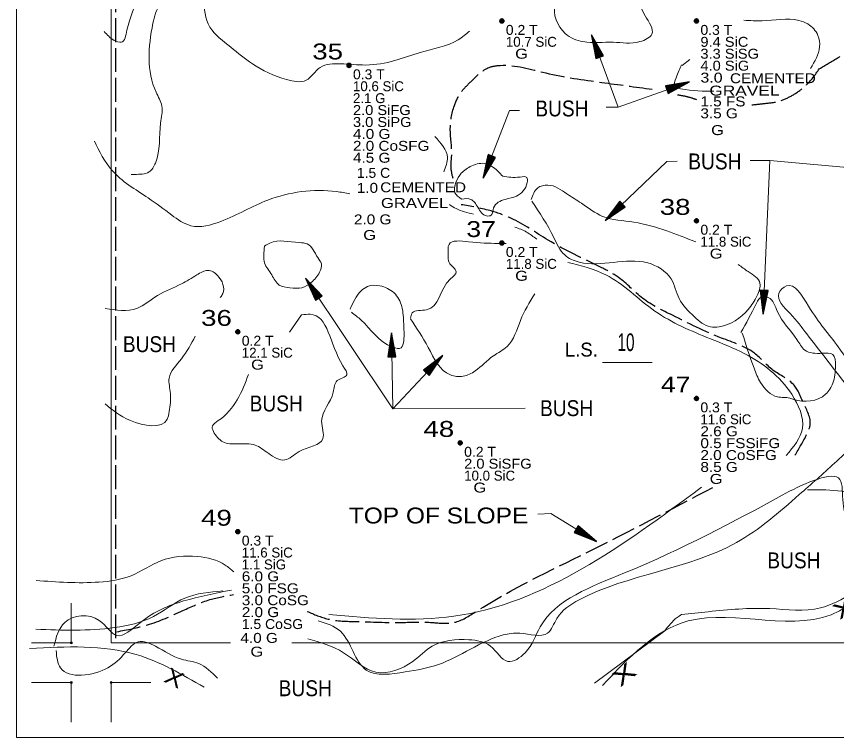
# Model space of a CAD drawing. Extents: x -496 to 480, y -450 to 700.
# Drawn here: x -450 to -37.5, y -450 to -87.1 of the extents above; entities that cross this region are included whole.
import ezdxf
from ezdxf.enums import TextEntityAlignment as Align

# ---------------------------------------------------------------- set-up
doc = ezdxf.new("R2010")
doc.units = 0
doc.header["$LTSCALE"] = 2
doc.header["$PDMODE"] = 32
doc.header["$PDSIZE"] = 1
doc.linetypes.add('LONG_DASHED', pattern=[7.5, 6, -1.5])
for name, color, linetype, lineweight in [('1', 7, 'Continuous', 13), ('2', 7, 'Continuous', 35), ('3', 7, 'Continuous', 13), ('4', 7, 'Continuous', 25)]:
    doc.layers.add(name, color=color, linetype=linetype, lineweight=lineweight)

msp = doc.modelspace()

# ---------------------------------------------------------------- linework, layer by layer
at = {"layer": '1'}
for p, q in [((-402.391, 402.339), (-402.391, -402.333)), ((-155.262, -261.192), (-130.262, -261.192)), ((-422.391, -402.333), (-422.391, -382.333)), ((-422.391, -402.333), (-442.391, -402.333)), ((-402.391, -402.333), (-342.324, -402.333)), ((-311.567, -402.333), (402.281, -402.333)), ((-422.391, -422.333), (-442.391, -422.333)), ((-422.391, -422.333), (-422.391, -442.333)), ((-402.391, -422.333), (-402.391, -442.333)), ((-450.017, -450.027), (449.983, -450.027))]:
    msp.add_line(p, q, dxfattribs=at)
for points in [[(449.983, -450.027), (449.983, 399.973), (449.983, 699.973), (-450.017, 699.973), (-450.017, 49.973), (-450.017, -450.027)], [(-402.391, -422.333), (-382.391, -422.333), (-402.391, -422.333)]]:
    msp.add_lwpolyline(points, dxfattribs=at)
for p in [(-422.391, -402.333), (-422.391, -422.333), (-402.391, -422.333)]:
    msp.add_point(p, dxfattribs=at)
at = {"layer": '2', "linetype": 'LONG_DASHED', "lineweight": 25}
msp.add_line((-400, -400), (-400, 302.339), dxfattribs=at)
at = {"layer": '2'}
for centre in [(-205.849, -89.361), (-107.989, -89.361), (-282.739, -111.711), (-107.989, -189.936), (-205.849, -201.111), (-338.659, -245.811), (-107.989, -279.336), (-226.819, -301.686), (-338.659, -346.386)]:
    msp.add_circle(centre, 1, dxfattribs=at)
for points in [[(-205.86, -88.474), (-205.129, -88.878), (-204.978, -89.727), (-205.663, -90.255), (-206.472, -90.024), (-206.758, -89.266), (-206.511, -88.704), (-205.938, -88.536), (-205.264, -89.03), (-205.281, -89.772), (-205.798, -90.03), (-206.32, -89.861), (-206.545, -89.215), (-205.961, -88.749), (-205.523, -89.283), (-205.562, -89.766), (-206.191, -89.631), (-206.045, -88.996), (-205.753, -89.547)], [(-108, -88.474), (-107.269, -88.878), (-107.118, -89.727), (-107.803, -90.255), (-108.612, -90.024), (-108.898, -89.266), (-108.651, -88.704), (-108.078, -88.536), (-107.404, -89.03), (-107.421, -89.772), (-107.938, -90.03), (-108.46, -89.861), (-108.685, -89.215), (-108.101, -88.749), (-107.663, -89.283), (-107.702, -89.766), (-108.331, -89.631), (-108.185, -88.996), (-107.893, -89.547)], [(-282.75, -110.824), (-282.019, -111.228), (-281.868, -112.077), (-282.553, -112.605), (-283.362, -112.374), (-283.648, -111.616), (-283.401, -111.054), (-282.828, -110.886), (-282.154, -111.38), (-282.171, -112.122), (-282.688, -112.38), (-283.21, -112.211), (-283.435, -111.565), (-282.851, -111.099), (-282.413, -111.633), (-282.452, -112.116), (-283.081, -111.981), (-282.935, -111.346), (-282.643, -111.897)], [(-108, -189.049), (-107.269, -189.453), (-107.118, -190.302), (-107.803, -190.83), (-108.612, -190.599), (-108.898, -189.841), (-108.651, -189.279), (-108.078, -189.111), (-107.404, -189.605), (-107.421, -190.347), (-107.938, -190.605), (-108.46, -190.436), (-108.685, -189.79), (-108.101, -189.324), (-107.663, -189.858), (-107.702, -190.341), (-108.331, -190.206), (-108.185, -189.571), (-107.893, -190.122)], [(-205.86, -200.224), (-205.129, -200.628), (-204.978, -201.477), (-205.663, -202.005), (-206.472, -201.774), (-206.758, -201.016), (-206.511, -200.454), (-205.938, -200.286), (-205.264, -200.78), (-205.281, -201.522), (-205.798, -201.78), (-206.32, -201.611), (-206.545, -200.965), (-205.961, -200.499), (-205.523, -201.033), (-205.562, -201.516), (-206.191, -201.381), (-206.045, -200.746), (-205.753, -201.297)], [(-338.67, -244.924), (-337.939, -245.328), (-337.788, -246.177), (-338.473, -246.705), (-339.282, -246.474), (-339.568, -245.716), (-339.321, -245.154), (-338.748, -244.986), (-338.074, -245.48), (-338.091, -246.222), (-338.608, -246.48), (-339.13, -246.311), (-339.355, -245.665), (-338.771, -245.199), (-338.333, -245.733), (-338.372, -246.216), (-339.001, -246.081), (-338.855, -245.446), (-338.563, -245.997)], [(-108, -278.449), (-107.269, -278.853), (-107.118, -279.702), (-107.803, -280.23), (-108.612, -279.999), (-108.898, -279.241), (-108.651, -278.679), (-108.078, -278.511), (-107.404, -279.005), (-107.421, -279.747), (-107.938, -280.005), (-108.46, -279.836), (-108.685, -279.19), (-108.101, -278.724), (-107.663, -279.258), (-107.702, -279.741), (-108.331, -279.606), (-108.185, -278.971), (-107.893, -279.522)], [(-226.83, -300.799), (-226.099, -301.203), (-225.948, -302.052), (-226.633, -302.58), (-227.442, -302.349), (-227.728, -301.591), (-227.481, -301.029), (-226.908, -300.861), (-226.234, -301.355), (-226.251, -302.097), (-226.768, -302.355), (-227.29, -302.186), (-227.515, -301.54), (-226.931, -301.074), (-226.493, -301.608), (-226.532, -302.091), (-227.161, -301.956), (-227.015, -301.321), (-226.723, -301.872)], [(-338.67, -345.499), (-337.939, -345.903), (-337.788, -346.752), (-338.473, -347.28), (-339.282, -347.049), (-339.568, -346.291), (-339.321, -345.729), (-338.748, -345.561), (-338.074, -346.055), (-338.091, -346.797), (-338.608, -347.055), (-339.13, -346.886), (-339.355, -346.24), (-338.771, -345.774), (-338.333, -346.308), (-338.372, -346.791), (-339.001, -346.656), (-338.855, -346.021), (-338.563, -346.572)]]:
    msp.add_spline(points, degree=3, dxfattribs=at)
at = {"layer": '2', "linetype": 'LONG_DASHED', "lineweight": 25}
for points in [[(-46.213, -113.44), (-37.202, -108.011), (-28.328, -103.466), (-16.725, -100.739), (-6.714, -99.603), (-5.46, -99.466)], [(-230.408, -168.6), (-231.437, -162.433), (-231.094, -157.294), (-231.78, -144.275), (-229.722, -131.941), (-225.949, -124.746), (-221.147, -119.607), (-212.229, -112.754), (-206.74, -111.727), (-183.759, -115.495), (-155.632, -120.292), (-130.25, -123.718)], [(-80.171, -131.598), (-73.997, -130.913), (-65.764, -129.542), (-59.247, -126.459), (-53.073, -122.005), (-46.213, -113.44)], [(-117.559, -126.459), (-112.413, -127.487), (-107.954, -128.857)], [(-58.437, -307.961), (-52.485, -297.343), (-50.784, -292.671), (-54.185, -281.629), (-58.863, -272.71), (-69.493, -265.065), (-78.847, -256.571), (-95.43, -248.926), (-120.092, -237.459), (-134.974, -228.965), (-147.305, -218.347), (-156.234, -213.25), (-182.596, -199.66), (-201.305, -188.617), (-211.935, -184.795), (-226.392, -181.822)], [(-303.779, -386.532), (-293.149, -390.354), (-279.117, -391.628), (-256.156, -392.053), (-241.699, -392.053), (-233.195, -392.478), (-229.794, -392.053), (-218.738, -386.532), (-163.037, -356.802), (-99.682, -324.1)], [(-399.449, -396.725), (-384.142, -393.327), (-366.283, -386.107), (-352.677, -380.586), (-340.771, -378.038)]]:
    msp.add_spline(points, degree=3, dxfattribs=at)
at = {"layer": '3'}
for p, q in [((-115.121, -111.726), (-111.273, -108.701)), ((-312.726, -246.028), (-306.569, -237.269)), ((-123.946, -396.28), (-159.286, -422.632))]:
    msp.add_line(p, q, dxfattribs=at)
for points in [[(-405.865, -94.67), (-400.768, -99.124), (-397.265, -100.078), (-394.398, -94.034), (-389.302, -77.808), (-387.709, -27.222), (-386.117, -18.314), (-377.517, -13.224), (-373.695, -15.133), (-364.458, -27.222), (-360.954, -33.267), (-359.361, -63.491), (-359.043, -73.99), (-363.183, -76.535), (-373.376, -78.762), (-377.517, -81.308), (-381.339, -90.534), (-379.746, -125.212), (-376.88, -132.211), (-377.517, -140.801), (-380.065, -160.845), (-383.25, -165.299), (-390.576, -166.571), (-392.345, -166.607)], [(-222.064, -94.436), (-227.814, -98.806), (-246.925, -105.169), (-259.666, -109.305), (-274.317, -111.532), (-287.058, -110.895), (-297.251, -112.804), (-304.258, -119.167), (-314.132, -118.849), (-331.332, -110.895), (-342.161, -102.624), (-352.672, -92.443), (-352.991, -61.582), (-351.717, -53.947)], [(-171.436, -58.401), (-164.429, -56.174), (-153.281, -56.174), (-142.133, -66.355), (-133.851, -86.716), (-130.348, -95.942), (-136.4, -99.76), (-149.777, -100.078), (-165.066, -99.76), (-173.985, -95.624), (-179.081, -80.989), (-173.348, -71.445), (-171.755, -59.037)], [(-84.103, -88.974), (-74.903, -89.31), (-56.461, -89.088), (-52.017, -90.863), (-46.907, -96.634), (-46.018, -102.404), (-50.623, -113.272)], [(-99.282, -124.751), (-116.009, -123.488), (-118.898, -122.379), (-118.231, -117.94), (-115.565, -111.504)], [(-239.609, -147.485), (-233.205, -158.023), (-235.009, -165.254)], [(-410.822, -149.827), (-402.028, -164.468), (-383.748, -178.431), (-371.919, -187.023), (-362.242, -192.393), (-347.187, -190.245), (-323.531, -179.505), (-289.121, -175.208), (-282.297, -176.356)], [(-226.078, -178.965), (-229.459, -175.789), (-228.952, -170.557), (-226.248, -165.999), (-221.01, -162.286), (-213.575, -161.274), (-210.026, -163.13), (-205.423, -167.503)], [(-226.078, -178.965), (-221.488, -179.173), (-217.941, -183.133), (-213.559, -187.509), (-211.265, -187.092), (-210.013, -183.341), (-204.171, -179.173), (-198.538, -177.506), (-193.113, -170.629), (-193.322, -168.128), (-196.66, -167.92), (-205.423, -167.503)], [(-191.126, -179.272), (-187.827, -173.414), (-182.696, -171.95), (-173.166, -176.343), (-165.836, -181.102), (-155.207, -187.692), (-139.447, -190.62), (-122.953, -195.014), (-108.348, -200.566)], [(-86.95, -211.951), (-81.903, -215.515), (-76.039, -221.372), (-77.505, -227.596), (-81.903, -234.552), (-96.564, -243.338), (-100.962, -243.338), (-109.026, -238.213), (-116.723, -229.06), (-120.754, -219.176), (-132.483, -211.122), (-166.936, -210.756), (-174.266, -207.095), (-179.764, -198.308), (-190.759, -180.004)], [(-232.139, -181.803), (-228.904, -183.801), (-220.095, -186.529)], [(-199.396, -193.069), (-193.419, -195.616), (-188.351, -199.186)], [(-325.167, -202.695), (-322.492, -201.137), (-307.778, -200.914), (-303.765, -201.582), (-298.414, -208.485), (-296.631, -211.603), (-297.522, -215.834), (-301.758, -220.955), (-306.44, -223.627), (-312.459, -223.627), (-317.81, -222.291), (-321.6, -217.17), (-325.167, -211.157), (-325.167, -202.695)], [(-251.82, -238.992), (-250.928, -236.32), (-243.794, -234.761), (-231.755, -219.174), (-228.857, -215.611), (-230.195, -213.384), (-232.424, -210.935), (-232.87, -206.926), (-232.424, -201.805), (-222.615, -200.469), (-207.678, -201.359), (-203.722, -201.411)], [(-172.722, -210.874), (-153.632, -217.097), (-128.9, -235.356), (-100.942, -249.319), (-83.737, -256.837), (-60.081, -277.244), (-54.704, -294.429), (-62.794, -308.026)], [(-405.351, -234.023), (-389.429, -234.023), (-379.031, -227.532), (-367.008, -221.689), (-359.209, -217.145), (-353.685, -214.873), (-348.811, -217.47), (-346.212, -226.558), (-347.468, -228.548)], [(-282.198, -234.348), (-276.674, -225.26), (-273.424, -222.988), (-267.25, -222.663), (-260.102, -226.233), (-256.202, -233.049), (-255.227, -241.813), (-255.227, -250.251), (-256.527, -253.822), (-260.752, -253.497), (-276.674, -239.865), (-281.548, -235.97)], [(-25.045, -283.284), (-31.126, -274.748), (-52.532, -246.859), (-60.908, -236.633), (-66.492, -226.408), (-62.769, -222.689), (-51.601, -232.915), (-36.71, -253.366), (-25.542, -266.381), (-1.344, -271.029), (59.151, -269.17), (76.834, -267.311), (88.933, -264.522), (91.725, -263.592), (101.963, -260.803), (141.052, -260.803), (168.042, -271.959), (185.632, -271.816)], [(-189.29, -226.613), (-196.531, -240.106), (-203.219, -253.244), (-210.13, -257.92), (-219.271, -265.491), (-225.29, -268.164), (-231.755, -267.496), (-242.902, -253.689), (-251.82, -239.215)], [(-85.592, -246.145), (-77.732, -231.425), (-75.113, -228.154), (-71.838, -228.481), (-67.253, -235.678), (-57.428, -249.743), (-53.498, -254.977), (-44.656, -256.612), (-39.417, -257.267), (-38.107, -262.827), (-39.417, -271.659), (-43.019, -277.22), (-59.066, -279.837), (-61.031, -279.183), (-67.253, -278.529), (-75.767, -271.332), (-79.042, -264.136), (-84.937, -246.472)], [(-306.569, -237.269), (-302.344, -236.944), (-285.772, -262.909), (-283.823, -267.453), (-288.697, -270.375), (-290.646, -276.217), (-296.495, -290.822), (-295.845, -299.586), (-307.868, -306.077), (-315.017, -310.296), (-323.141, -307.051), (-329.965, -302.831), (-338.738, -302.182), (-346.212, -301.208), (-348.811, -298.936), (-351.411, -293.094), (-348.486, -290.498), (-333.258, -267.239)], [(-360.034, -247.993), (-367.008, -259.339), (-373.182, -269.076), (-372.532, -276.866), (-373.182, -285.954), (-374.157, -289.849), (-392.679, -290.498), (-405.351, -282.059)], [(-298.323, -391.257), (-287.066, -396.527), (-274.036, -416.049), (-254.492, -416.978), (-237.739, -413.26), (-205.165, -398.386), (-196.789, -397.457), (-182.828, -397.457), (-178.175, -390.02), (-167.007, -380.723), (-87.898, -351.905), (-56.254, -327.736), (-38.571, -311.932), (-29.348, -303.089)], [(-155.247, -423.81), (-112.142, -391.328), (-35.973, -386.256), (9.729, -352.442), (55.43, -355.824), (74.049, -337.226), (197.613, -337.226), (216.232, -359.205), (263.626, -357.515), (267.5, -350.576)], [(88.896, -303.619), (49.044, -310.618), (19.602, -316.132), (-0.64, -326.242), (-10.761, -328.08), (-42.964, -325.323), (-52.165, -325.323)], [(-303.447, -400.25), (-285.473, -407.314), (-269.167, -417.086), (-250.688, -411.657), (-240.904, -404.057), (-222.425, -400.799), (-211.554, -404.057), (-202.858, -411.657), (-194.162, -407.314), (-186.552, -394.284), (-144.158, -367.14), (-64.804, -328.052), (-48.498, -320.451), (-36.541, -319.365), (-34.367, -330.223), (-31.106, -341.081), (-16.974, -329.138), (-8.336, -324.238)], [(-105.388, -324.019), (-229.979, -388.946), (-292.861, -388.127)], [(88.718, -334.024), (76.16, -334.535), (70.748, -335.693), (65.336, -342.257), (58.378, -348.821), (51.807, -352.296), (33.638, -351.524), (20.109, -349.98), (14.31, -349.593), (4.646, -351.138), (-2.698, -358.474), (-29.371, -377.394), (-45.607, -384.73), (-71.12, -385.116), (-102.045, -386.66), (-115.443, -388.108)], [(-340.738, -366.543), (-345.037, -363.169), (-359.016, -358.873), (-377.296, -361.021), (-392.35, -368.539), (-408.48, -371.761), (-440.132, -370.951)], [(-440.174, -395.508), (-400.61, -394.668), (-381.066, -389.09), (-365.244, -379.794), (-346.274, -376.213)], [(-431.137, -404.057), (-425.701, -392.113), (-408.309, -391.027), (-399.612, -398.628), (-387.655, -392.113), (-365.914, -381.255), (-341.779, -375.801)], [(-123.946, -396.28), (-117.726, -389.601), (-115.443, -388.108)], [(-443.356, -405.126), (-389.736, -408.235), (-355.532, -424.724)], [(-348.927, -420.064), (-358.305, -412.743), (-367.001, -410.571), (-380.046, -404.057), (-388.742, -401.885), (-395.264, -407.314), (-403.961, -414.914), (-427.875, -414.914), (-430.05, -406.228)]]:
    msp.add_spline(points, degree=3, dxfattribs=at)
at = {"layer": '4', "lineweight": 13}
for p, q in [((-147.335, -132.749), (-111.512, -119.922)), ((-71.087, -159.656), (-74.464, -236.991)), ((-260.731, -284.569), (-261.439, -246.399)), ((-260.731, -284.569), (-235.609, -257.709))]:
    msp.add_line(p, q, dxfattribs=at)
for points in [[(-153.418, -132.749), (-147.335, -132.749), (-160.853, -96.292)], [(-197.015, -134.437), (-202.084, -134.437), (-215.265, -168.531)], [(-117.639, -159.897), (-122.945, -160.138), (-153.819, -189.771)], [(-80.976, -159.656), (-71.087, -159.656), (-24.776, -163.751)], [(-194.21, -284.216), (-260.731, -284.569), (-304.606, -218.832)], [(-187.701, -337.511), (-181.249, -337.31), (-158.264, -351.407)]]:
    msp.add_lwpolyline(points, dxfattribs=at)
at = {"layer": '4'}
for points in [[(-160.853, -96.292), (-158.557, -108.239), (-154.806, -106.848)], [(-111.512, -119.922), (-123.483, -122.084), (-122.135, -125.85)], [(-215.265, -168.531), (-209.072, -158.06), (-212.803, -156.617)], [(-153.819, -189.771), (-143.776, -182.904), (-146.546, -180.018)], [(-304.606, -218.832), (-299.608, -229.924), (-296.281, -227.703)], [(-74.464, -236.991), (-71.942, -225.09), (-75.938, -224.916)], [(-261.439, -246.399), (-263.216, -258.434), (-259.217, -258.36)], [(-235.609, -257.709), (-245.266, -265.107), (-242.345, -267.839)], [(-158.264, -351.407), (-167.447, -343.429), (-169.539, -346.838)]]:
    msp.add_lwpolyline(points, close=True, dxfattribs=at)
for points in [[(-158.48, -108.106), (-160.655, -96.83), (-155.017, -106.753), (-158.332, -108.004), (-160.399, -97.521), (-155.245, -106.63), (-158.251, -107.791), (-160.128, -98.251), (-155.517, -106.523), (-158.094, -107.595), (-159.84, -99.087), (-155.782, -106.367), (-157.965, -107.315), (-159.493, -100.09), (-156.093, -106.275), (-157.797, -107.023), (-159.115, -101.17), (-156.495, -106.125), (-157.666, -106.697), (-158.739, -102.37), (-156.858, -105.891), (-157.535, -106.303), (-158.201, -103.761), (-157.336, -105.654)], [(-123.351, -122.162), (-112.052, -120.114), (-122.037, -125.64), (-123.251, -122.311), (-112.746, -120.363), (-121.912, -125.414), (-123.039, -122.395), (-113.478, -120.625), (-121.802, -125.143), (-122.844, -122.554), (-114.318, -120.904), (-121.643, -124.879), (-122.566, -122.686), (-115.325, -121.239), (-121.547, -124.569), (-122.276, -122.857), (-116.409, -121.605), (-121.393, -124.17), (-121.952, -122.992), (-117.613, -121.968), (-121.155, -123.809), (-121.559, -123.127), (-119.01, -122.49), (-120.912, -123.334)], [(-209.218, -158.108), (-215.057, -167.996), (-212.709, -156.828), (-209.396, -158.087), (-214.791, -167.309), (-212.619, -157.072), (-209.598, -158.192), (-214.511, -166.583), (-212.486, -157.332), (-209.846, -158.236), (-214.172, -165.766), (-212.39, -157.624), (-210.127, -158.36), (-213.768, -164.785), (-212.219, -157.899), (-210.447, -158.468), (-213.336, -163.725), (-212.017, -158.278), (-210.761, -158.624), (-212.823, -162.577), (-211.9, -158.693), (-211.12, -158.833), (-212.304, -161.179), (-211.699, -159.188)], [(-143.929, -182.887), (-153.404, -189.374), (-146.55, -180.25), (-144.081, -182.792), (-152.873, -188.864), (-146.572, -180.508), (-144.309, -182.802), (-152.311, -188.325), (-146.561, -180.8), (-144.552, -182.736), (-151.659, -187.728), (-146.599, -181.106), (-144.859, -182.73), (-150.877, -187.01), (-146.559, -181.427), (-145.195, -182.692), (-150.037, -186.233), (-146.537, -181.855), (-145.545, -182.701), (-149.087, -185.41), (-146.606, -182.281), (-145.959, -182.739), (-148.025, -184.362), (-146.634, -182.815)], [(-299.564, -229.776), (-304.288, -219.31), (-296.508, -227.659), (-299.444, -229.643), (-303.879, -219.923), (-296.758, -227.592), (-299.414, -229.418), (-303.447, -220.57), (-297.048, -227.551), (-299.307, -229.19), (-302.974, -221.317), (-297.342, -227.461), (-299.246, -228.888), (-302.404, -222.213), (-297.666, -227.443), (-299.15, -228.565), (-301.786, -223.176), (-298.091, -227.39), (-299.098, -228.218), (-301.143, -224.256), (-298.498, -227.247), (-299.062, -227.804), (-300.298, -225.485), (-299.018, -227.126)], [(-72.065, -225.183), (-74.438, -236.418), (-75.781, -225.085), (-72.24, -225.219), (-74.406, -235.682), (-75.619, -225.287), (-72.398, -225.384), (-74.372, -234.905), (-75.409, -225.491), (-72.619, -225.504), (-74.312, -234.022), (-75.225, -225.738), (-72.846, -225.712), (-74.243, -232.963), (-74.975, -225.944), (-73.114, -225.916), (-74.172, -231.821), (-74.663, -226.238), (-73.362, -226.165), (-74.052, -230.569), (-74.419, -226.594), (-73.635, -226.477), (-74.008, -229.078), (-74.071, -226.998)], [(-263.099, -258.334), (-261.429, -246.973), (-259.384, -258.201), (-262.926, -258.287), (-261.415, -247.71), (-259.558, -258.009), (-262.779, -258.113), (-261.401, -248.488), (-259.78, -257.819), (-262.566, -257.979), (-261.405, -249.372), (-259.979, -257.584), (-262.352, -257.757), (-261.409, -250.434), (-260.242, -257.394), (-262.097, -257.537), (-261.408, -251.578), (-260.571, -257.12), (-261.866, -257.274), (-261.45, -252.835), (-260.837, -256.78), (-261.612, -256.945), (-261.401, -254.325), (-261.21, -256.397)], [(-245.113, -265.116), (-236.001, -258.127), (-242.354, -267.608), (-244.956, -265.203), (-236.504, -258.665), (-242.346, -267.349), (-244.729, -265.18), (-237.036, -259.234), (-242.372, -267.058), (-244.483, -265.233), (-237.656, -259.865), (-242.351, -266.751), (-244.175, -265.222), (-238.397, -260.624), (-242.408, -266.431), (-243.839, -265.242), (-239.194, -261.446), (-242.453, -266.005), (-243.489, -265.214), (-240.099, -262.318), (-242.407, -265.576), (-243.078, -265.155), (-241.103, -263.422), (-242.408, -265.042)], [(-167.426, -343.581), (-158.752, -351.107), (-169.314, -346.784), (-167.479, -343.752), (-159.38, -350.722), (-169.059, -346.739), (-167.412, -343.97), (-160.044, -350.315), (-168.779, -346.655), (-167.414, -344.221), (-160.787, -349.835), (-168.474, -346.614), (-167.342, -344.521), (-161.679, -349.26), (-168.172, -346.495), (-167.294, -344.854), (-162.643, -348.644), (-167.764, -346.365), (-167.196, -345.191), (-163.68, -347.932), (-167.334, -346.324), (-167.055, -345.582), (-164.962, -347.17), (-166.811, -346.216)]]:
    msp.add_lwpolyline(points, dxfattribs=at)

# ---------------------------------------------------------------- texts
at = {"layer": '1', "width": 0.65}
msp.add_text('10', height=8.89, dxfattribs=at).set_placement((-143.426, -255.494), align=Align.CENTER)
at = {"layer": '1'}
msp.add_text('L.S.', height=7, dxfattribs=at).set_placement((-165.882, -258.253), align=Align.CENTER)
at = {"layer": '2'}
for s, width, p in [('0.2 T      ', 1.05, (-203.849, -96.361)), ('0.3 T      ', 1.05, (-105.989, -96.361)), ('9.4 SiC    ', 1.1, (-105.989, -102.361)), ('3.3 SiSG   ', 1.1, (-105.989, -108.361)), ('  G        ', 1.25, (-203.849, -108.361)), ('4.0 SiG    ', 1.1, (-105.989, -114.361)), ('0.3 T      ', 1.05, (-280.739, -118.711)), ('3.0        ', 1.2, (-105.989, -120.361)), ('CEMENTED   ', 1.15, (-91.122, -120.683)), ('    GRAVEL ', 1.3, (-111.162, -126.905)), ('1.5 FS     ', 1.15, (-105.989, -132.361)), ('2.0 SiFG   ', 1.1, (-280.739, -136.711)), ('3.5 G      ', 1.15, (-105.989, -138.361)), ('3.0 SiPG   ', 1.1, (-280.739, -142.711)), ('4.0 G      ', 1.15, (-280.739, -148.711)), ('  G        ', 1.25, (-105.281, -146.792)), ('2.0 CoSFG  ', 1.15, (-280.739, -154.711)), ('4.5 G      ', 1.15, (-280.739, -160.711)), ('1.5 C      ', 1.05, (-278.812, -168.312)), ('1.0        ', 1.15, (-278.812, -175.861)), ('CEMENTED   ', 1.15, (-267.032, -175.566)), ('GRAVEL     ', 1.25, (-266.676, -183.471)), ('2.0 G      ', 1.15, (-280.24, -191.733)), ('0.2 T      ', 1.05, (-105.989, -196.936)), ('  G        ', 1.25, (-280.24, -199.578)), ('0.2 T      ', 1.05, (-203.849, -208.111)), ('  G        ', 1.25, (-105.989, -208.936)), ('  G        ', 1.25, (-203.849, -220.111)), ('0.2 T      ', 1.05, (-336.659, -252.811)), ('  G        ', 1.25, (-336.659, -264.811)), ('0.3 T      ', 1.05, (-105.989, -286.336)), ('2.6 G      ', 1.15, (-105.989, -298.336)), ('0.5 FSSiFG ', 1.15, (-105.989, -304.336)), ('0.2 T      ', 1.05, (-224.819, -308.686)), ('2.0 CoSFG  ', 1.15, (-105.989, -310.336)), ('2.0 SiSFG  ', 1.1, (-224.819, -314.686)), ('8.5 G      ', 1.15, (-105.989, -316.336)), ('  G        ', 1.25, (-105.989, -322.336)), ('  G        ', 1.25, (-224.819, -326.686)), ('0.3 T      ', 1.05, (-336.659, -353.386)), ('6.0 G      ', 1.15, (-336.659, -371.386)), ('5.0 FSG    ', 1.15, (-336.659, -377.386)), ('3.0 CoSG   ', 1.15, (-336.659, -383.386)), ('2.0 G      ', 1.15, (-336.659, -389.386)), ('1.5 CoSG   ', 1.05, (-336.659, -395.386)), ('4.0 G      ', 1.15, (-337.332, -402.355)), ('  G        ', 1.25, (-336.989, -409.256))]:
    msp.add_text(s, height=5, dxfattribs=dict(at, width=width)).set_placement(p)
for s, p in [('10.7 SiC   ', (-203.849, -102.361)), ('10.6 SiC   ', (-280.739, -124.711)), ('2.1 G      ', (-280.739, -130.711)), ('11.8 SiC   ', (-105.989, -202.936)), ('11.8 SiC   ', (-203.849, -214.111)), ('12.1 SiC   ', (-336.659, -258.811)), ('11.6 SiC   ', (-105.989, -292.336)), ('10.0 SiC   ', (-224.819, -320.686)), ('11.6 SiC   ', (-336.659, -359.386)), ('1.1 SiG    ', (-336.659, -365.386))]:
    msp.add_text(s, height=5, dxfattribs=at).set_placement(p)
for s, width, p in [(' 35', 1.3, (-285.739, -108.711)), (' 38', 1.3, (-110.989, -186.936)), (' 37', 1.25, (-208.849, -198.111)), (' 36', 1.3, (-341.659, -242.811)), (' 47', 1.25, (-110.989, -276.336)), (' 48', 1.3, (-229.819, -298.686)), (' 49', 1.3, (-341.659, -343.386))]:
    msp.add_text(s, height=8, dxfattribs=dict(at, width=width)).set_placement(p, align=Align.RIGHT)
at = {"layer": '3'}
for rotation, width, p in [(33.04, 1.45, (-31.657, -388.093)), (38.241, 1.6, (-141.919, -421.365)), (333.965, 1.25, (-372.359, -423.609))]:
    msp.add_text('X', height=8, rotation=rotation, dxfattribs=dict(at, width=width)).set_placement(p, align=Align.CENTER)
at = {"layer": '4'}
for s, width, p in [('BUSH', 0.9, (-175.658, -137.401)), ('BUSH', 0.9, (-98.736, -164.051)), ('BUSH', 0.9, (-383.114, -256.026)), ('BUSH', 0.9, (-319.35, -285.882)), ('BUSH', 0.9, (-173.284, -288.226)), ('TOP OF SLOPE', 1.15, (-237.69, -342.255)), ('BUSH', 0.9, (-58.977, -364.832)), ('BUSH', 0.9, (-304.737, -429.186))]:
    msp.add_text(s, height=8, dxfattribs=dict(at, width=width)).set_placement(p, align=Align.CENTER)

doc.saveas('drawing.dxf')
